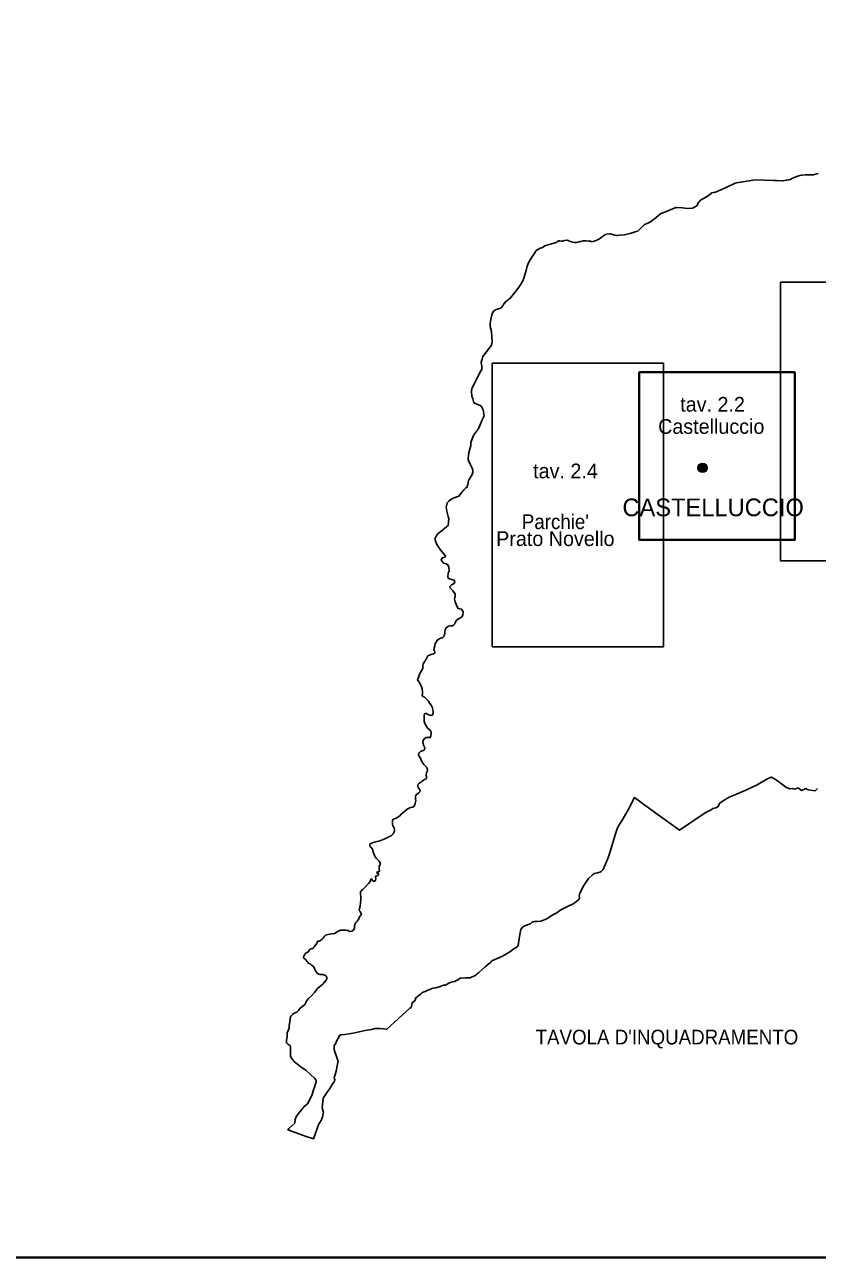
# Model space of a CAD drawing. Extents: x 650468 to 655025, y 889970 to 891591.
# Drawn here: x 652602 to 653140, y 889970 to 890806 of the extents above; entities that cross this region are included whole.
import ezdxf
from ezdxf.enums import TextEntityAlignment as Align

# ---------------------------------------------------------------- set-up
doc = ezdxf.new("R2010")
doc.units = 0
doc.header["$LTSCALE"] = 5.6
doc.layers.add('61', color=7, linetype='Continuous', lineweight=35)

msp = doc.modelspace()

# ---------------------------------------------------------------- hatches: boundary and pattern name
at = {"layer": '61'}
msp.add_hatch(color=256, dxfattribs=at).paths.add_polyline_path([(653064.94, 890505.49, 1), (653058.58, 890505.49, 1)])

# ---------------------------------------------------------------- linework, layer by layer
at = {"layer": '61', "lineweight": 40}
for points in [[(653618.27, 891591.08), (653618.27, 889969.62), (652568.28, 889969.62), (652568.28, 891591.08)], [(653018.83, 890570.32), (653124.35, 890570.32), (653124.35, 890456.46), (653018.83, 890456.46)]]:
    msp.add_lwpolyline(points, close=True, dxfattribs=at)
at = {"layer": '61', "lineweight": 25}
for points in [[(653084.78, 890698.77), (653087.7, 890699.29), (653097.4, 890700.82), (653109.78, 890700.45), (653111.82, 890700.3), (653116.22, 890700.09), (653118.72, 890700.54), (653120.2, 890700.94), (653121.52, 890701.01), (653122.34, 890701.7), (653125.1, 890702.97), (653127.7, 890703.82), (653129.06, 890704.06), (653131.58, 890704.13), (653134.9, 890704.13), (653136.74, 890704.13), (653140.26, 890705.14)], [(652986.98, 890658.73), (652989.56, 890659.73), (652991.92, 890660.77), (652993.9, 890662.33), (652995.94, 890663.86), (652996.82, 890663.94), (652998.56, 890664.22), (652999.2, 890664.18), (653003.14, 890663.06), (653003.78, 890663.06), (653005.52, 890663.33), (653008.82, 890663.57), (653010.56, 890663.94), (653012.6, 890664.49), (653016.16, 890665.49), (653017.94, 890666.02), (653022.14, 890670.25), (653026.04, 890672.22), (653029.1, 890674.38), (653033.36, 890677.98), (653036.18, 890678.86), (653039.36, 890680.21), (653043.62, 890682.06), (653044.32, 890682.1), (653048.14, 890681.94), (653051.4, 890681.38), (653054.84, 890681.69), (653056.82, 890682.61), (653058.48, 890683.98), (653058.42, 890684.46), (653059.18, 890685.58), (653060.34, 890687.01), (653064.54, 890689.42), (653067.62, 890691.58), (653067.84, 890692.13), (653070.56, 890692.49), (653072.06, 890693.26), (653078.3, 890695.98), (653083.96, 890698.49), (653084.78, 890698.77)], [(652938.2, 890629.54), (652939.82, 890632.33), (652940.58, 890634.06), (652941.46, 890636.97), (652942.04, 890639.22), (652942.8, 890642.18), (652943.74, 890644.49), (652944.84, 890646.46), (652946.36, 890649.06), (652947.44, 890650.62), (652949, 890652.85), (652951.66, 890654.46), (652952.82, 890654.7), (652953.84, 890655.33), (652954.86, 890656.06), (652956.92, 890656.69), (652961.7, 890658.18), (652962.92, 890658.54), (652963.42, 890658.9), (652964.24, 890659.54), (652964.9, 890659.54), (652966.08, 890659.29), (652966.78, 890659.29), (652968.06, 890659.73), (652970.18, 890659.86), (652971.14, 890659.54), (652972.28, 890659.05), (652973.88, 890658.54), (652975.1, 890658.3), (652976.18, 890658.3), (652977.84, 890658.66), (652979.24, 890659.05), (652980.78, 890659.42), (652981.98, 890659.49), (652982.76, 890659.49), (652984.34, 890659.29), (652985.82, 890659.17), (652986.98, 890658.73)], [(652913, 890544.69), (652911.98, 890546.49), (652911.36, 890547.54), (652908.16, 890548.77), (652906.64, 890549.62), (652905.98, 890552.3), (652905.36, 890553.97), (652905.02, 890557.3), (652905.28, 890559.3), (652905.68, 890560.17), (652911.1, 890570.82), (652912.06, 890572.06), (652912.1, 890572.89), (652911.98, 890574.13), (652911.66, 890577.05), (652912.24, 890579.22), (652912.82, 890580.94), (652914.54, 890583.22), (652917.02, 890586.7), (652918.62, 890588.62), (652919, 890590.98), (652918.76, 890594.38), (652918.5, 890597.86), (652917.8, 890601.38), (652917.72, 890603.5), (652918.1, 890606.1), (652918.82, 890609.14), (652919.84, 890611.57), (652920.34, 890612.01), (652921.76, 890612.74), (652924.36, 890613.54), (652925.18, 890614.05), (652926.14, 890615.22), (652927.22, 890616.82), (652928.44, 890618.45), (652929.98, 890619.5), (652931.76, 890620.93), (652934.18, 890624.14), (652935.92, 890626.38), (652938.2, 890629.54)], [(652889.58, 890470.98), (652889.26, 890472.46), (652888.3, 890476.06), (652887.92, 890478.66), (652887.98, 890479.53), (652888.62, 890481.58), (652889.52, 890482.62), (652891.18, 890484.06), (652894.5, 890485.42), (652896.34, 890486.1), (652898.78, 890489.06), (652899.48, 890489.82), (652899.92, 890490.49), (652901.14, 890491.74), (652902.02, 890492.17), (652902.16, 890492.98), (652902.54, 890493.97), (652902.68, 890495.46), (652902.92, 890496.82), (652904.14, 890498.54), (652905.56, 890500.85), (652905.86, 890502.53), (652905.86, 890503.74), (652905.56, 890505.1), (652905.04, 890506.1), (652904.14, 890507.98), (652902.86, 890510.77), (652902.74, 890511.89), (652903.24, 890515.49), (652904.2, 890518.94), (652904.66, 890520.62), (652904.6, 890522.61), (652906.24, 890526.82), (652907.4, 890528.69), (652908.68, 890530.61), (652909.44, 890531.26), (652910.72, 890534.13), (652912.38, 890538.02), (652913.6, 890540.7), (652913, 890544.69)], [(652896.92, 890409.78), (652895.72, 890410.14), (652894.82, 890412.21), (652893.86, 890414.42), (652893.54, 890416.22), (652893.98, 890418.34), (652893.98, 890419.82), (652892.46, 890421.93), (652890.54, 890423.9), (652890.36, 890424.97), (652891.44, 890425.97), (652893.22, 890427.01), (652893.68, 890428.3), (652893.1, 890429.18), (652890.92, 890429.86), (652889.32, 890430.22), (652888.88, 890431.22), (652889.14, 890433.82), (652889.78, 890435.26), (652889.66, 890438.01), (652889, 890439.61), (652887.86, 890440.22), (652886.08, 890440.73), (652884.92, 890441.97), (652884.54, 890443.21), (652885.3, 890444.33), (652886.9, 890444.86), (652887.42, 890445.3), (652886.96, 890446.06), (652883.72, 890449.9), (652881.48, 890453.37), (652880.4, 890456.34), (652880.4, 890457.77), (652881.08, 890459.14), (652882.48, 890460.82), (652885.36, 890463.1), (652888.1, 890465.34), (652889.18, 890466.22), (652889.52, 890468.62), (652889.58, 890470.98)], [(652873.16, 890373.78), (652874.36, 890375.58), (652874.9, 890377.01), (652875.5, 890377.81), (652876.46, 890378.3), (652878.04, 890378.85), (652879.34, 890379.21), (652879.94, 890379.58), (652880.06, 890380.06), (652879.88, 890380.94), (652879.58, 890381.94), (652879.74, 890383.09), (652880.12, 890384.58), (652880.18, 890385.57), (652880.54, 890386.41), (652881.74, 890388.3), (652883.12, 890389.42), (652884.14, 890389.9), (652885.52, 890390.25), (652886.18, 890390.86), (652886.6, 890391.78), (652886.84, 890392.73), (652887, 890393.85), (652887.08, 890395.3), (652887.38, 890395.98), (652887.8, 890396.85), (652888.66, 890397.54), (652889.52, 890398.06), (652890.76, 890398.09), (652892.24, 890398.21), (652892.9, 890398.66), (652893.62, 890399.5), (652893.96, 890400.45), (652895.06, 890402.14), (652897.1, 890403.42), (652898.46, 890404.26), (652899.22, 890405.5), (652899.36, 890407.78), (652898.28, 890409.46), (652896.92, 890409.78)], [(652874.3, 890330.3), (652873.38, 890331.85), (652872.96, 890333.3), (652872.98, 890334.14), (652872.98, 890335.98), (652873.02, 890337.66), (652873.22, 890338.5), (652873.76, 890338.74), (652874.4, 890338.62), (652875.14, 890338.21), (652876.16, 890337.69), (652877.72, 890337.41), (652878.62, 890337.74), (652878.96, 890338.66), (652879.02, 890339.77), (652878.8, 890341.14), (652878.48, 890342.58), (652877.72, 890344.25), (652876.82, 890345.53), (652875.86, 890346.98), (652874.48, 890348.38), (652873.16, 890349.81), (652872.08, 890350.33), (652871.68, 890350.98), (652871.74, 890351.86), (652871.8, 890353.33), (652871.58, 890355.34), (652871.18, 890357.01), (652870.34, 890358.41), (652869.5, 890360.02), (652868.48, 890361.57), (652868.52, 890362.3), (652869.22, 890363.7), (652869.74, 890365.26), (652870.18, 890366.25), (652871.64, 890368.25), (652872, 890369.45), (652871.92, 890371.02), (652872.34, 890372.29), (652873.16, 890373.78)], [(652874.6, 890295.85), (652874.36, 890296.66), (652874.36, 890297.29), (652874.6, 890298.37), (652875.02, 890299.42), (652875.22, 890300.29), (652874.94, 890301.33), (652874.42, 890302.34), (652873.24, 890303.61), (652872.56, 890304.3), (652871.96, 890304.9), (652871.58, 890305.86), (652870.98, 890306.94), (652870.34, 890308.3), (652869.48, 890309.7), (652869.12, 890310.34), (652869.06, 890310.66), (652869.06, 890311.13), (652869.56, 890312.1), (652870.46, 890312.82), (652872.22, 890313.5), (652873.24, 890314.06), (652873.44, 890314.85), (652873.04, 890316.05), (652872.76, 890316.58), (652872.38, 890317.61), (652872.02, 890318.98), (652872.32, 890320.18), (652872.74, 890321.25), (652873.56, 890322.02), (652874.36, 890322.41), (652875.22, 890322.42), (652876.5, 890322.29), (652877, 890322.46), (652877.46, 890323.57), (652877.62, 890324.86), (652877.52, 890326.82), (652877.08, 890327.42), (652875.42, 890328.61), (652874.3, 890330.3)], [(652851.36, 890264.46), (652851.36, 890265.46), (652851.48, 890266.38), (652851.98, 890266.89), (652852.88, 890267.14), (652853.96, 890267.62), (652855.06, 890268.25), (652856.22, 890269.06), (652857.34, 890270.38), (652859.58, 890272.1), (652861.3, 890273.74), (652862.66, 890274.49), (652863.62, 890274.94), (652864.98, 890275.13), (652865.74, 890275.45), (652866.42, 890276.21), (652866.68, 890276.78), (652866.74, 890277.78), (652867.02, 890278.66), (652867.18, 890279.7), (652867.12, 890280.89), (652867.1, 890282.05), (652867.32, 890282.98), (652867.78, 890283.73), (652869.2, 890284.94), (652869.96, 890285.62), (652870.16, 890286.42), (652869.82, 890287.42), (652868.94, 890288.46), (652868.58, 890289.74), (652868.84, 890290.62), (652869.44, 890291.3), (652870.98, 890292.05), (652871.68, 890292.7), (652872.38, 890293.42), (652873.16, 890293.81), (652874, 890294.05), (652874.48, 890294.49), (652874.6, 890295.06), (652874.6, 890295.85)], [(653113.56, 890292.34), (653110.54, 890294.25), (653108.3, 890295.57), (653106.26, 890294.53), (653100.98, 890291.7), (653098.74, 890290.26), (653091.02, 890286.58), (653083.22, 890283.18), (653079.92, 890281.86), (653075.24, 890279.29), (653073.48, 890277.89), (653072.04, 890275.3), (653070.68, 890274.78), (653068.74, 890274.18), (653067.66, 890273.21), (653066.3, 890272.54), (653064.66, 890272.06), (653063.44, 890271.34), (653046.1, 890259.42), (653025.92, 890274.1), (653015.62, 890281.78), (653011.62, 890273.78), (653006.92, 890265.94), (653004.56, 890262.06), (653003.8, 890260.41), (653002.16, 890255.65), (652999.72, 890247.02), (652998.84, 890244.25), (652998.14, 890242.14), (652996.86, 890238.66), (652995.58, 890235.45), (652994.24, 890232.9), (652993.1, 890231.42), (652992.02, 890230.9), (652990.44, 890230.66), (652988.2, 890230.09), (652987.04, 890229.3), (652984.42, 890226.62), (652981.16, 890221.9), (652978.48, 890216.82)], [(653139.74, 890287.9), (653138.1, 890286.21), (653133.5, 890286.94), (653131.86, 890287.73), (653128.98, 890286.38), (653126.54, 890288.18), (653124.3, 890287.33), (653122.74, 890287.73), (653120.78, 890287.62), (653118.26, 890288.74), (653116.3, 890290.18), (653113.56, 890292.34)], [(652841.9, 890229.81), (652841.46, 890230.05), (652841.14, 890230.13), (652840.88, 890230.49), (652840.88, 890230.66), (652841.14, 890231.1), (652841.6, 890231.22), (652842.22, 890231.29), (652842.68, 890231.9), (652842.36, 890233.02), (652842.48, 890235.01), (652843.12, 890235.94), (652843.06, 890237.17), (652842.56, 890238.22), (652841.46, 890239.34), (652840.38, 890240.46), (652839.8, 890241.33), (652839.04, 890242.89), (652838.66, 890244.22), (652838.14, 890245.61), (652837.82, 890246.66), (652837.32, 890247.29), (652836.28, 890248.26), (652836.02, 890249.01), (652836.1, 890249.94), (652836.8, 890250.42), (652837.94, 890250.86), (652839.3, 890251.3), (652840.94, 890251.77), (652842.92, 890252.33), (652846.24, 890253.57), (652848.86, 890254.93), (652850.66, 890255.93), (652851.8, 890257.02), (652852.82, 890258.77), (652852.82, 890259.26), (652852.52, 890261.13), (652851.74, 890262.54), (652851.42, 890263.66), (652851.36, 890264.46)], [(652825.72, 890194.42), (652825.98, 890195.61), (652826.54, 890196.85), (652827.56, 890197.78), (652828.34, 890198.94), (652828.78, 890200.18), (652829.74, 890201.5), (652830.22, 890201.89), (652830.36, 890202.57), (652829.96, 890203.26), (652829.46, 890204.25), (652828.94, 890205.06), (652829, 890206.34), (652829.46, 890207.97), (652829.66, 890210.13), (652829.9, 890212.49), (652829.9, 890214.46), (652829.78, 890215.89), (652829.66, 890216.82), (652829.78, 890217.69), (652830.3, 890218.25), (652831.32, 890219.22), (652833.22, 890221.17), (652835.2, 890223.21), (652836.3, 890224.69), (652836.68, 890226.06), (652836.8, 890226.46), (652837.32, 890226.26), (652837.82, 890225.46), (652838.26, 890224.9), (652839.48, 890224.98), (652839.98, 890225.65), (652840.06, 890226.58), (652839.98, 890227.57), (652840.06, 890228.33), (652840.32, 890228.38), (652840.94, 890228.62), (652841.54, 890228.86), (652841.9, 890229.25), (652841.9, 890229.81)], [(652978.48, 890216.82), (652978.16, 890215.05), (652978.22, 890213.57), (652977.8, 890212.54), (652976.32, 890211.13), (652974.02, 890209.53), (652970.7, 890207.85), (652967.06, 890206.13), (652964.84, 890205.09), (652962.98, 890203.41), (652960.7, 890202.34), (652959.02, 890201.42), (652956.02, 890199.26), (652953.98, 890198.46), (652952.14, 890197.85), (652949.46, 890197.46), (652947.54, 890197.46), (652946.26, 890197.09), (652945.16, 890195.98), (652943.52, 890195.42), (652940.78, 890194.42), (652939.56, 890193.74), (652938.54, 890192.21), (652938.2, 890191.02), (652937.84, 890188.82), (652937.02, 890182.94), (652936.58, 890181.33), (652935.74, 890180.22), (652934.34, 890179.41), (652932.74, 890178.22), (652931.14, 890176.93), (652928.84, 890175.62), (652926.16, 890173.97), (652922.46, 890172.34), (652918.88, 890170.74), (652917.62, 890169.49), (652915.94, 890168.06), (652914.28, 890166.7), (652912.3, 890164.9), (652909.76, 890162.81)], [(652791.32, 890174.09), (652791.94, 890175.06), (652792.52, 890175.94), (652793.6, 890176.54), (652794.5, 890177.1), (652795.22, 890178.3), (652795.64, 890178.7), (652796.34, 890178.89), (652797.3, 890179.26), (652798.38, 890180.37), (652799.02, 890181.34), (652799.78, 890182.34), (652800.3, 890183.22), (652800.68, 890184.09), (652801.2, 890184.26), (652801.96, 890184.26), (652802.6, 890184.7), (652803.68, 890185.57), (652804.32, 890186.33), (652804.9, 890186.94), (652805.34, 890187.69), (652806.04, 890188.18), (652806.8, 890188.42), (652807.82, 890188.66), (652809.04, 890188.9), (652810.52, 890189.17), (652812.04, 890189.46), (652813.2, 890189.98), (652814.42, 890190.82), (652815.38, 890191.26), (652816.26, 890191.58), (652817.66, 890191.7), (652818.88, 890191.7), (652819.96, 890191.58), (652821.26, 890191.33), (652822.2, 890190.82), (652823.86, 890190.9), (652825.02, 890191.7), (652825.58, 890193.06), (652825.72, 890194.42)], [(652781.72, 890129.21), (652781.98, 890131.62), (652782.56, 890133.22), (652783.64, 890134.46), (652784.72, 890135.34), (652786.52, 890136.06), (652787.66, 890137.06), (652788.74, 890138.61), (652790.66, 890139.97), (652791.94, 890141.22), (652792.76, 890142.58), (652793.36, 890144.01), (652794.44, 890145.37), (652796.48, 890147.02), (652798.58, 890149.38), (652800.68, 890152.01), (652801.84, 890153.14), (652804.16, 890155.06), (652805.42, 890156.42), (652806.84, 890158.34), (652806.96, 890159.46), (652806.38, 890160.38), (652805.48, 890161.06), (652804.28, 890161.57), (652803.2, 890161.57), (652802.36, 890161.5), (652801.46, 890161.69), (652800.5, 890162.25), (652799.74, 890163.34), (652798.78, 890164.9), (652798.34, 890166.41), (652797.32, 890167.5), (652796.54, 890168.01), (652795.64, 890168.7), (652794.62, 890169.13), (652793.6, 890170.42), (652792.4, 890171.78), (652791.26, 890172.66), (652791.12, 890173.21), (652791.32, 890174.09)], [(652909.76, 890162.81), (652907.54, 890160.9), (652904.22, 890159.22), (652903.64, 890159.29), (652901.22, 890159.22), (652899.44, 890159.1), (652897.9, 890159.29), (652897.2, 890158.78), (652895.36, 890157.74), (652893.5, 890156.82), (652892.42, 890156.7), (652891.32, 890156.45), (652889.66, 890155.77), (652887.36, 890154.34), (652886.14, 890154.34), (652883.14, 890153.22), (652880.84, 890152.49), (652878.98, 890152.34), (652876.5, 890151.49), (652875, 890150.82), (652873.54, 890150.01), (652872.14, 890149.58), (652871.42, 890149.14), (652870.52, 890148.29), (652869, 890147.02), (652867.02, 890145.54), (652867.02, 890144.62), (652866.14, 890143.3), (652864.78, 890142.46), (652864.28, 890140.1), (652864.08, 890139.22), (652863.26, 890138.74), (652847.68, 890124.45), (652843.16, 890124.89), (652840.92, 890125.01), (652839.64, 890124.82), (652837.16, 890124.34), (652832.88, 890123.53), (652824.7, 890121.86), (652819.02, 890120.74)], [(652787.92, 890053.33), (652783.58, 890055.09), (652780.56, 890056.26), (652781.04, 890057.02), (652785.3, 890060.7), (652785.5, 890063.1), (652786.14, 890065.02), (652787.66, 890067.14), (652789.64, 890069.81), (652791.56, 890071.98), (652792.9, 890073.09), (652793.8, 890073.7), (652794.94, 890075.86), (652797.06, 890080.02), (652797.94, 890083.38), (652798.52, 890085.22), (652799.3, 890087.34), (652799.72, 890088.54), (652799.6, 890089.9), (652798.58, 890091.26), (652796.16, 890093.54), (652792.58, 890096.65), (652789.52, 890098.74), (652784.96, 890102.29), (652783.32, 890104.09), (652782.22, 890106.01), (652782.16, 890108.98), (652782.3, 890112.45), (652781.78, 890113.42), (652780.44, 890114.18), (652779.48, 890115.1), (652779.62, 890116.98), (652780, 890119.46), (652780.06, 890120.94), (652779.92, 890121.94), (652780.12, 890122.5), (652780.88, 890123.93), (652781.28, 890125.22), (652781.4, 890126.97), (652781.72, 890129.21)], [(652819.02, 890120.74), (652816.66, 890120.57), (652815.5, 890120.18), (652815.14, 890119.14), (652813.52, 890116.29), (652812.7, 890114.62), (652811.8, 890113.3), (652811.86, 890110.7), (652812.38, 890109.17), (652813.22, 890106.54), (652814.1, 890103.86), (652814.54, 890102.94), (652814.1, 890100.77), (652813.14, 890095.98), (652812.62, 890093.46), (652812.12, 890092.41), (652811.86, 890091.66), (652812.2, 890090.78), (652812.38, 890090.17), (652812.08, 890089.18), (652811.6, 890088.46), (652811.06, 890087.58), (652809.98, 890085.94), (652808.52, 890083.62), (652807.1, 890081.69), (652805.8, 890079.66), (652804.7, 890078.18), (652804.24, 890075.58), (652803.92, 890073.06), (652803.66, 890071.14), (652804.16, 890069.41), (652804.56, 890068.14), (652804.5, 890067.21), (652803.88, 890064.94), (652803.28, 890062.85), (652802.22, 890061.05), (652801.54, 890060.17), (652797.84, 890050.14), (652792.8, 890051.7), (652787.92, 890053.33)]]:
    msp.add_lwpolyline(points, dxfattribs=at)
for points in [[(653114.54, 890631.33), (653265.86, 890631.33), (653265.86, 890442.31), (653114.54, 890442.31)], [(653035.24, 890576.4), (653035.24, 890383.97), (652919.14, 890383.97), (652919.14, 890576.4)]]:
    msp.add_lwpolyline(points, close=True, dxfattribs=at)
at = {"layer": '61', "lineweight": 13}
msp.add_circle((653061.76, 890505.49), 3.18, dxfattribs=at)

# ---------------------------------------------------------------- texts
at = {"layer": '61'}
for s, p in [('tav. 2.2', (653046.63, 890543.52)), ('tav. 2.4', (652946.86, 890498.29))]:
    msp.add_text(s, height=10, dxfattribs=at).set_placement(p)
for s, height, p in [('Castelluccio', 10, (653067.68, 890528.49)), ('CASTELLUCCIO', 12, (653068.94, 890472.57)), ('Prato Novello', 10, (652961.92, 890452.34))]:
    msp.add_text(s, height=height, dxfattribs=at).set_placement(p, align=Align.CENTER)
at = {"layer": '61', "width": 0.95}
msp.add_text("Parchie'", height=10, dxfattribs=at).set_placement((652961.92, 890463.84), align=Align.CENTER)
msp.add_text("TAVOLA D'INQUADRAMENTO", height=10, dxfattribs=at).set_placement((652948.51, 890114.1))

doc.saveas('drawing.dxf')
